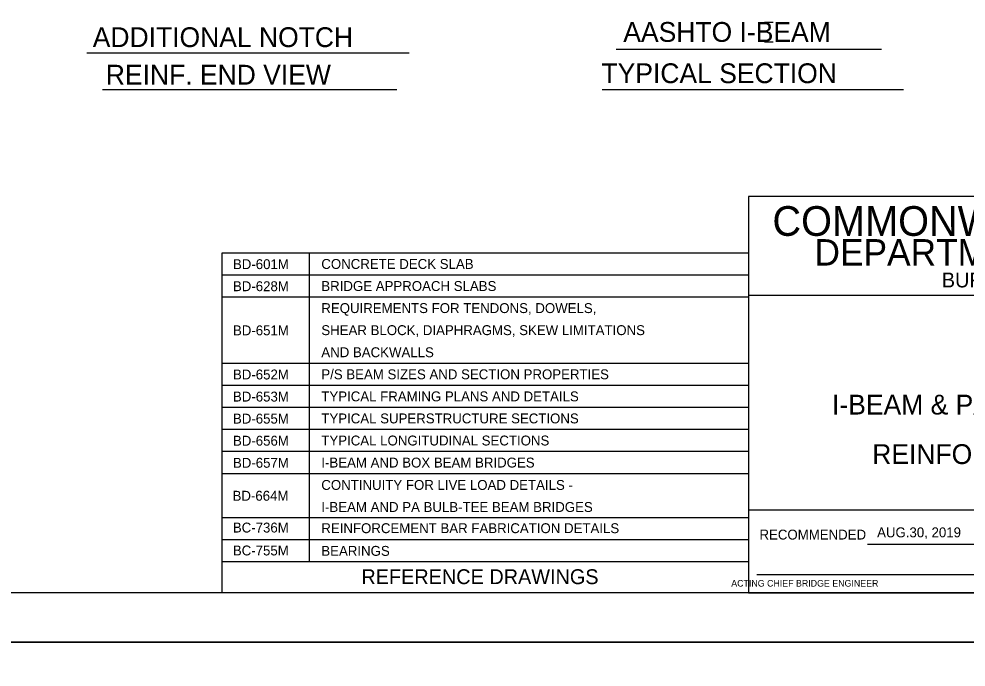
# Model space of a CAD drawing. Extents: x 637933 to 640019, y 298854 to 300042.
# Drawn here: x 638388.8 to 638675.9, y 299440.6 to 299636.9 of the extents above; entities that cross this region are included whole.
import ezdxf

# ---------------------------------------------------------------- set-up
doc = ezdxf.new("R2010")
doc.units = 0
doc.layers.add('1', color=7, linetype='Continuous')
doc.layers.add('PLT-BNDY', color=7, linetype='Continuous')

msp = doc.modelspace()

# ---------------------------------------------------------------- linework, layer by layer
at = {"layer": '1'}
for p, q in [((638614.77, 299636), (638617.37, 299636)), ((638614.77, 299630), (638617.37, 299630)), ((638650.22, 299627.67), (638569.85, 299627.67)), ((638507.11, 299626.55), (638409.45, 299626.55)), ((638503.37, 299615.5), (638414.16, 299615.5)), ((638656.95, 299615.5), (638565.63, 299615.5)), ((638809.94, 299583.12), (638609.94, 299583.12)), ((638609.94, 299583.12), (638609.94, 299463.12)), ((638450.36, 299566.04), (638450.36, 299463.12)), ((638609.94, 299566.04), (638450.36, 299566.04)), ((638476.8, 299566.04), (638476.8, 299472.45)), ((638609.94, 299559.36), (638450.36, 299559.36)), ((638609.94, 299552.67), (638450.36, 299552.67)), ((638809.94, 299553.12), (638609.94, 299553.12)), ((638609.94, 299532.62), (638450.36, 299532.62)), ((638609.94, 299525.93), (638450.36, 299525.93)), ((638609.94, 299519.25), (638450.36, 299519.25)), ((638609.94, 299512.56), (638450.36, 299512.56)), ((638609.94, 299505.88), (638450.36, 299505.88)), ((638609.94, 299499.19), (638450.36, 299499.19)), ((638809.94, 299488.12), (638609.94, 299488.12)), ((638609.94, 299485.82), (638450.36, 299485.82)), ((638609.94, 299479.14), (638450.36, 299479.14)), ((638646.02, 299477.83), (638682.44, 299477.83)), ((638609.94, 299472.45), (638450.36, 299472.45)), ((638612.44, 299468.62), (638682.44, 299468.62)), ((638809.94, 299463.12), (638023.93, 299463.12)), ((638609.94, 299463.12), (638809.94, 299463.12))]:
    msp.add_line(p, q, dxfattribs=at)
at = {"layer": 'PLT-BNDY'}
for points in [[(637983.93, 300042.12), (638824.93, 300042.12), (638824.93, 299448.12), (637983.93, 299448.12)], [(637983.93, 299448.12), (638824.93, 299448.12), (638824.93, 298854.12), (637983.93, 298854.12)]]:
    msp.add_lwpolyline(points, close=True, dxfattribs=at)

# ---------------------------------------------------------------- texts
at = {"layer": '1'}
for s, height, p in [('AASHTO I-BEAM', 6, (638572, 299630.01)), ('ADDITIONAL NOTCH', 6, (638411.21, 299628.42)), ('REINF. END VIEW', 6, (638415.17, 299617.05)), ('TYPICAL SECTION', 6, (638565.39, 299617.5)), ('COMMONWEALTH OF PENNSYLVANIA', 9, (638617.19, 299571.24)), ('DEPARTMENT OF TRANSPORTATION', 8.0003, (638629.94, 299562.24)), ('CONCRETE DECK SLAB', 3, (638480.48, 299561.22)), ('BUREAU OF PROJECT DELIVERY', 4.5, (638668.53, 299555.62)), ('BRIDGE APPROACH SLABS', 3, (638480.48, 299554.54)), ('REQUIREMENTS FOR TENDONS, DOWELS,', 3, (638480.48, 299547.85)), ('SHEAR BLOCK, DIAPHRAGMS, SKEW LIMITATIONS', 3, (638480.48, 299541.17)), ('AND BACKWALLS', 3, (638480.48, 299534.48)), ('P/S BEAM SIZES AND SECTION PROPERTIES', 3, (638480.48, 299527.8)), ('TYPICAL FRAMING PLANS AND DETAILS', 3, (638480.48, 299521.11)), ('I-BEAM & PA BULB-TEE BEAM', 6, (638635.26, 299517.12)), ('TYPICAL SUPERSTRUCTURE SECTIONS', 3, (638480.48, 299514.43)), ('TYPICAL LONGITUDINAL SECTIONS', 3, (638480.48, 299507.74)), ('REINFORCEMENT DETAILS', 6, (638647.44, 299502.12)), ('I-BEAM AND BOX BEAM BRIDGES', 3, (638480.48, 299501.06)), ('CONTINUITY FOR LIVE LOAD DETAILS -', 3, (638480.48, 299494.28)), ('I-BEAM AND PA BULB-TEE BEAM BRIDGES', 3, (638480.48, 299487.6)), ('REINFORCEMENT BAR FABRICATION DETAILS', 3, (638480.48, 299481.18)), ('RECOMMENDED', 3, (638613.27, 299479.24)), ('AUG.30, 2019', 3, (638648.92, 299479.92)), ('BC-755M', 3, (638453.67, 299474.43)), ('BEARINGS', 3, (638480.48, 299474.31)), ('REFERENCE DRAWINGS', 4.5, (638492.62, 299465.74)), ('       ACTING CHIEF BRIDGE ENGINEER', 2.0002, (638599.52, 299464.99))]:
    msp.add_text(s, height=height, dxfattribs=at).set_placement(p)
for s, p in [('BD-601M', (638453.7, 299561.16)), ('BD-628M', (638453.7, 299554.48)), ('BD-651M', (638453.7, 299541.11)), ('BD-652M', (638453.7, 299527.74)), ('BD-653M', (638453.7, 299521.05)), ('BD-655M', (638453.7, 299514.37)), ('BD-656M', (638453.7, 299507.68)), ('BD-657M', (638453.7, 299500.99)), ('BD-664M', (638453.58, 299491)), ('BC-736M', (638453.67, 299481.37))]:
    msp.add_text(s, height=3, rotation=360, dxfattribs=at).set_placement(p)

doc.saveas('drawing.dxf')
